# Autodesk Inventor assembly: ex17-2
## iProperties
Shininess: 64.0
Length Units: 11272
Angle Units: 11279
Time Units: 11290
Mass Units: 11286
Length Display Precision: 3
Angle Display Precision: 2
Compacted: True
Part Number: ex17-2
Document SubType Name: Assembly
Created: 2002-11
Designer: E. MOSS
Density: 0.0
Volumn: 0.0
Area: 0.0
PropertySet Name: Model Information
Control State: 0
Master: False
Checked Out: False
Author: E. MOSS
